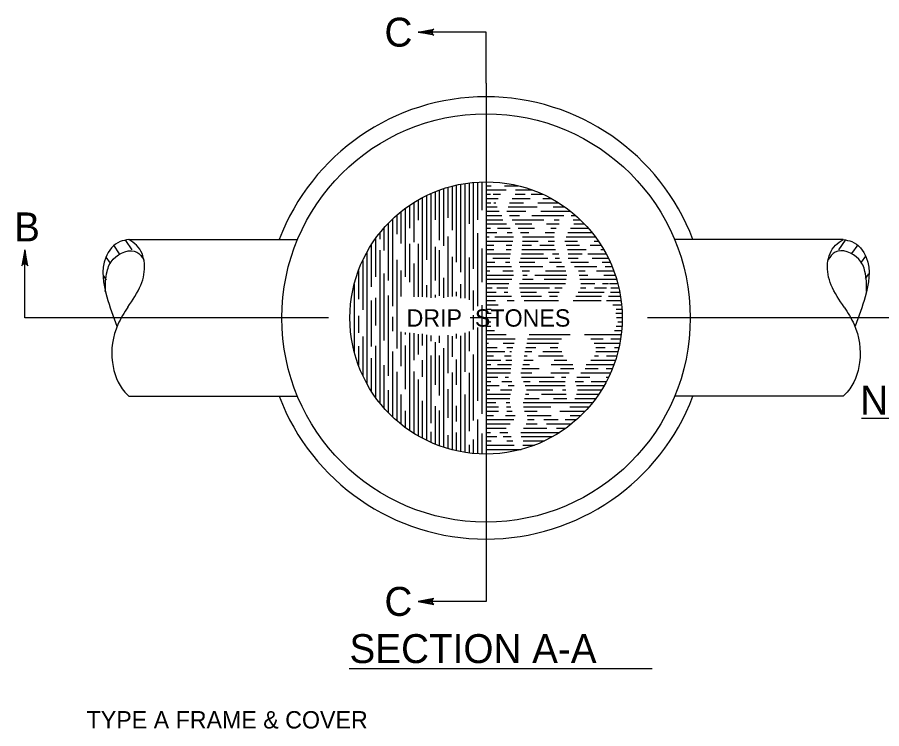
# Model space of a CAD drawing. Extents: x 0.2 to 7.1, y 1.2 to 11.2.
# Drawn here: x 0.3 to 3.289, y 8.396 to 10.856 of the extents above; entities that cross this region are included whole.
import ezdxf

# ---------------------------------------------------------------- set-up
doc = ezdxf.new("R2010")
doc.units = 0
for name, color, linetype in [('DETL-DIMS', 7, 'Continuous'), ('DETL-LINE', 7, 'Continuous'), ('DETL-NOTE', 7, 'Continuous'), ('DETL-PATT', 7, 'Continuous'), ('DETL-TITL', 7, 'Continuous')]:
    doc.layers.add(name, color=color, linetype=linetype)

msp = doc.modelspace()

# ---------------------------------------------------------------- linework, layer by layer
at = {"layer": 'DETL-DIMS'}
for p, q in [((1.9208, 10.8045), (1.6855, 10.8045)), ((1.9208, 10.628), (1.9208, 10.8045)), ((1.9208, 10.628), (1.9208, 9.0129)), ((0.3259, 9.8165), (0.3259, 10.0518)), ((0.5024, 9.8165), (0.3259, 9.8165)), ((1.3755, 9.8165), (0.5024, 9.8165)), ((3.3247, 9.8165), (2.4784, 9.8165)), ((1.9208, 9.0129), (1.9208, 8.8365)), ((1.9208, 8.8365), (1.6855, 8.8365))]:
    msp.add_line(p, q, dxfattribs=at)
for points in [[(1.6855, 10.8045), (1.7403, 10.8148), (1.7361, 10.8119), (1.7339, 10.8082), (1.7333, 10.8045), (1.7339, 10.8008), (1.7361, 10.7972), (1.7403, 10.7942), (1.6855, 10.8045), (1.7361, 10.7972), (1.7339, 10.8008), (1.6855, 10.8045), (1.7333, 10.8045), (1.7339, 10.8082), (1.6855, 10.8045), (1.7361, 10.8119)], [(0.3259, 10.0518), (0.3156, 9.997), (0.3186, 10.0012), (0.3222, 10.0034), (0.3259, 10.004), (0.3296, 10.0034), (0.3333, 10.0012), (0.3362, 9.997), (0.3259, 10.0518), (0.3333, 10.0012), (0.3296, 10.0034), (0.3259, 10.0518), (0.3259, 10.004), (0.3222, 10.0034), (0.3259, 10.0518), (0.3186, 10.0012)], [(1.6855, 8.8365), (1.7403, 8.8262), (1.7361, 8.8291), (1.7339, 8.8328), (1.7333, 8.8365), (1.7339, 8.8401), (1.7361, 8.8438), (1.7403, 8.8467), (1.6855, 8.8365), (1.7361, 8.8438), (1.7339, 8.8401), (1.6855, 8.8365), (1.7333, 8.8365), (1.7339, 8.8328), (1.6855, 8.8365), (1.7361, 8.8291)]]:
    msp.add_lwpolyline(points, dxfattribs=at)
at = {"layer": 'DETL-LINE'}
for p, q in [((0.6855, 10.0874), (1.2689, 10.0874)), ((3.1557, 10.0874), (2.5722, 10.0874)), ((0.6855, 9.5457), (1.2689, 9.5457)), ((3.1557, 9.5457), (2.5722, 9.5457))]:
    msp.add_line(p, q, dxfattribs=at)
for radius in [0.7059, 0.4706]:
    msp.add_circle((1.9208, 9.8165), radius, dxfattribs=at)
for start, end in [(20.7424, 159.2576), (200.7424, 339.2576)]:
    msp.add_arc((1.9208, 9.8165), 0.7647, start, end, dxfattribs=at)
for points in [[(0.6855, 10.0874), (0.6561, 10.0807), (0.606, 10.0252), (0.6096, 9.8901), (0.6447, 9.7881)], [(0.682, 9.8543), (0.7273, 9.9302), (0.7396, 10.0051), (0.7128, 10.0677), (0.6855, 10.0874)], [(3.1592, 9.8543), (3.1139, 9.9302), (3.1016, 10.0051), (3.1284, 10.0677), (3.1557, 10.0874)], [(3.1557, 10.0874), (3.1851, 10.0807), (3.2352, 10.0252), (3.2316, 9.8901), (3.1965, 9.7881)], [(0.6045, 9.9083), (0.6105, 9.9773), (0.6319, 10.0201), (0.7139, 10.0439), (0.7378, 10.0186)], [(3.2366, 9.9083), (3.2307, 9.9773), (3.2093, 10.0201), (3.1272, 10.0439), (3.1034, 10.0186)], [(0.682, 9.8543), (0.6477, 9.7937), (0.6288, 9.6626), (0.6719, 9.56), (0.6855, 9.5457)], [(3.1592, 9.8543), (3.1934, 9.7937), (3.2123, 9.6626), (3.1693, 9.56), (3.1557, 9.5457)]]:
    msp.add_spline(points, degree=3, dxfattribs=at)
at = {"layer": 'DETL-NOTE'}
msp.add_line((3.2189, 9.4698), (3.6066, 9.4698), dxfattribs=at)
at = {"layer": 'DETL-PATT'}
for p, q in [((1.8473, 10.2813), (1.8473, 9.8848)), ((1.862, 10.2834), (1.862, 10.1419)), ((1.8767, 10.285), (1.8767, 9.9859)), ((1.8914, 10.2862), (1.8914, 10.1556)), ((1.9061, 10.2869), (1.9061, 10.1891)), ((1.7443, 10.2528), (1.7443, 10.1563)), ((1.759, 10.2584), (1.759, 10.0855)), ((1.7737, 10.2635), (1.7737, 10.0657)), ((1.7884, 10.2681), (1.7884, 10.1632)), ((1.8031, 10.2722), (1.8031, 10.1205)), ((1.8178, 10.2757), (1.8178, 10.0093)), ((1.8325, 10.2788), (1.8325, 9.975)), ((1.9208, 10.2737), (1.938, 10.2737)), ((1.9208, 10.259), (1.9908, 10.259)), ((1.9846, 10.2737), (2.0323, 10.2737)), ((2.0223, 10.259), (2.081, 10.259)), ((1.6855, 10.2241), (1.6855, 10.1548)), ((1.7002, 10.2322), (1.7002, 9.8892)), ((1.7149, 10.2397), (1.7149, 10.0177)), ((1.7296, 10.2465), (1.7296, 9.8864)), ((1.9208, 10.2443), (1.9356, 10.2443)), ((1.9208, 10.2296), (1.9623, 10.2296)), ((1.9459, 10.2443), (1.9704, 10.2443)), ((2.0115, 10.2296), (2.0738, 10.2296)), ((2.0217, 10.2443), (2.0565, 10.2443)), ((2.0762, 10.2443), (2.1169, 10.2443)), ((2.1165, 10.2296), (2.1462, 10.2296)), ((1.6414, 10.1952), (1.6414, 9.9582)), ((1.6561, 10.2056), (1.6561, 10.1266)), ((1.6708, 10.2152), (1.6708, 10.0786)), ((1.9208, 10.2149), (1.9372, 10.2149)), ((1.9208, 10.2002), (1.9588, 10.2002)), ((1.9482, 10.2149), (1.9549, 10.2149)), ((1.9973, 10.2002), (2.0975, 10.2002)), ((2.0022, 10.2149), (2.0501, 10.2149)), ((2.0999, 10.2149), (2.1713, 10.2149)), ((2.1528, 10.2002), (2.1933, 10.2002)), ((1.612, 10.1716), (1.612, 10.1061)), ((1.6267, 10.1839), (1.6267, 10.0741)), ((1.9208, 10.1855), (1.9662, 10.1855)), ((1.9208, 10.1708), (1.9753, 10.1708)), ((1.9926, 10.1855), (2.0588, 10.1855)), ((2.0016, 10.1708), (2.0367, 10.1708)), ((2.0794, 10.1708), (2.1901, 10.1708)), ((2.1102, 10.1855), (2.2129, 10.1855)), ((2.2154, 10.1708), (2.2306, 10.1708)), ((1.5825, 10.1437), (1.5825, 9.946)), ((1.5973, 10.1583), (1.5973, 9.8575)), ((1.9208, 10.1561), (1.9788, 10.1561)), ((1.9208, 10.1414), (1.9915, 10.1414)), ((2.0114, 10.1561), (2.1204, 10.1561)), ((2.0219, 10.1414), (2.0786, 10.1414)), ((2.1299, 10.1414), (2.1741, 10.1414)), ((2.1568, 10.1561), (2.1735, 10.1561)), ((2.2222, 10.1561), (2.2466, 10.1561)), ((2.2244, 10.1414), (2.2613, 10.1414)), ((1.5531, 10.1103), (1.5531, 10.0893)), ((1.5678, 10.1278), (1.5678, 10.0497)), ((1.8914, 10.1091), (1.8914, 9.8575)), ((1.9208, 10.1267), (1.9364, 10.1267)), ((1.9208, 10.112), (1.9577, 10.112)), ((1.9601, 10.1267), (2.0037, 10.1267)), ((1.9941, 10.112), (2.0112, 10.112)), ((2.0315, 10.1267), (2.0881, 10.1267)), ((2.0403, 10.112), (2.0683, 10.112)), ((2.1252, 10.112), (2.1569, 10.112)), ((2.1449, 10.1267), (2.1636, 10.1267)), ((2.204, 10.112), (2.2871, 10.112)), ((2.2132, 10.1267), (2.2747, 10.1267)), ((0.674, 10.0847), (0.6961, 10.0523)), ((1.5384, 10.0909), (1.5384, 9.959)), ((1.6561, 10.0733), (1.6561, 9.9407)), ((1.6855, 10.0725), (1.6855, 9.89)), ((1.7884, 10.0984), (1.7884, 9.8897)), ((1.9208, 10.0972), (1.9317, 10.0972)), ((1.9208, 10.0825), (2.0128, 10.0825)), ((1.9514, 10.0972), (2.0152, 10.0972)), ((2.0462, 10.0825), (2.1007, 10.0825)), ((2.0468, 10.0972), (2.1562, 10.0972)), ((2.1354, 10.0825), (2.1573, 10.0825)), ((2.1928, 10.0825), (2.2365, 10.0825)), ((2.1972, 10.0972), (2.2985, 10.0972)), ((2.2942, 10.0825), (2.309, 10.0825)), ((3.1404, 10.0515), (3.164, 10.0855)), ((0.6322, 10.0677), (0.6525, 10.038)), ((1.509, 10.0443), (1.509, 9.5887)), ((1.5237, 10.0691), (1.5237, 9.9239)), ((1.5531, 10.0504), (1.5531, 9.5228)), ((1.7443, 10.0626), (1.7443, 9.946)), ((1.759, 10.0512), (1.759, 9.8928)), ((1.9061, 10.0565), (1.9061, 9.9399)), ((1.9208, 10.0678), (1.9475, 10.0678)), ((1.9208, 10.0531), (1.9482, 10.0531)), ((1.9901, 10.0678), (2.0103, 10.0678)), ((1.9901, 10.0531), (2.0078, 10.0531)), ((2.0444, 10.0531), (2.1604, 10.0531)), ((2.0456, 10.0678), (2.0778, 10.0678)), ((2.107, 10.0678), (2.156, 10.0678)), ((2.1973, 10.0678), (2.2444, 10.0678)), ((2.2029, 10.0531), (2.2674, 10.0531)), ((2.2808, 10.0678), (2.3186, 10.0678)), ((2.3171, 10.0531), (2.3276, 10.0531)), ((3.1859, 10.0397), (3.2067, 10.0696)), ((0.6066, 10.027), (0.621, 10.0059)), ((1.4943, 10.0155), (1.4943, 9.8444)), ((1.612, 10.0177), (1.612, 9.7113)), ((1.8031, 10.0276), (1.8031, 9.8906)), ((1.862, 10.0253), (1.862, 9.8793)), ((1.9208, 10.0384), (2.0052, 10.0384)), ((1.9208, 10.0237), (1.923, 10.0237)), ((1.9443, 10.0237), (2.0027, 10.0237)), ((2.0395, 10.0237), (2.1339, 10.0237)), ((2.0429, 10.0384), (2.1189, 10.0384)), ((2.1505, 10.0384), (2.1719, 10.0384)), ((2.1599, 10.0237), (2.1751, 10.0237)), ((2.205, 10.0384), (2.2531, 10.0384)), ((2.205, 10.0237), (2.2389, 10.0237)), ((2.2729, 10.0384), (2.3358, 10.0384)), ((2.2879, 10.0237), (2.3433, 10.0237)), ((3.2182, 10.0089), (3.2333, 10.0306)), ((1.6708, 10.0047), (1.6708, 9.8895)), ((1.9208, 10.009), (1.9514, 10.009)), ((1.9208, 9.9943), (2.0085, 9.9943)), ((1.9877, 10.009), (2.0034, 10.009)), ((2.0353, 10.009), (2.0896, 10.009)), ((2.039, 9.9943), (2.1165, 9.9943)), ((2.1402, 10.009), (2.1819, 10.009)), ((2.1639, 9.9943), (2.192, 9.9943)), ((2.2141, 10.009), (2.2753, 10.009)), ((2.2271, 9.9943), (2.3037, 9.9943)), ((2.3219, 10.009), (2.3502, 10.009)), ((2.3321, 9.9943), (2.3565, 9.9943)), ((0.5967, 9.9631), (0.6079, 9.9468)), ((1.4796, 9.9803), (1.4796, 9.8818)), ((1.5678, 9.9697), (1.5678, 9.7385)), ((1.6267, 9.9803), (1.6267, 9.8903)), ((1.7737, 9.9552), (1.7737, 9.8864)), ((1.9208, 9.9796), (1.934, 9.9796)), ((1.9208, 9.9649), (2.0152, 9.9649)), ((1.9783, 9.9796), (2.0147, 9.9796)), ((2.0452, 9.9796), (2.0707, 9.9796)), ((2.0475, 9.9649), (2.0628, 9.9649)), ((2.0896, 9.9649), (2.1998, 9.9649)), ((2.1268, 9.9796), (2.1966, 9.9796)), ((2.2407, 9.9796), (2.2634, 9.9796)), ((2.2428, 9.9649), (2.2721, 9.9649)), ((2.3021, 9.9796), (2.3622, 9.9796)), ((2.3282, 9.9649), (2.3674, 9.9649)), ((3.2328, 9.9525), (3.2444, 9.9692)), ((1.4649, 9.9332), (1.4649, 9.6998)), ((1.7149, 9.93), (1.7149, 9.8889)), ((1.8325, 9.9331), (1.8325, 9.8845)), ((1.9208, 9.9502), (2.0101, 9.9502)), ((1.9208, 9.9355), (2, 9.9355)), ((2.0367, 9.9355), (2.1949, 9.9355)), ((2.0464, 9.9502), (2.0841, 9.9502)), ((2.1212, 9.9502), (2.1979, 9.9502)), ((2.2451, 9.9502), (2.372, 9.9502)), ((2.2481, 9.9355), (2.2966, 9.9355)), ((2.3234, 9.9355), (2.3444, 9.9355)), ((2.3472, 9.9355), (2.3761, 9.9355)), ((1.5825, 9.8942), (1.5825, 9.6167)), ((1.7443, 9.8965), (1.7443, 9.8872)), ((1.8178, 9.9064), (1.8178, 9.8914)), ((1.8767, 9.9109), (1.8767, 9.8427)), ((1.9208, 9.9208), (1.9419, 9.9208)), ((1.9208, 9.9061), (1.9554, 9.9061)), ((1.9585, 9.9208), (1.9966, 9.9208)), ((1.9838, 9.9061), (1.9961, 9.9061)), ((2.0364, 9.9208), (2.1402, 9.9208)), ((2.0396, 9.9061), (2.0952, 9.9061)), ((2.137, 9.9061), (2.1739, 9.9061)), ((2.1591, 9.9208), (2.1837, 9.9208)), ((2.2393, 9.9061), (2.3286, 9.9061)), ((2.2472, 9.9208), (2.2658, 9.9208)), ((2.2958, 9.9208), (2.337, 9.9208)), ((2.3509, 9.9061), (2.3828, 9.9061)), ((2.3517, 9.9208), (2.3797, 9.9208)), ((1.5237, 9.8767), (1.5237, 9.7179)), ((1.5384, 9.8866), (1.5384, 9.79)), ((1.9208, 9.8914), (2.0091, 9.8914)), ((1.9208, 9.8767), (1.953, 9.8767)), ((1.9933, 9.8767), (2.0182, 9.8767)), ((2.0424, 9.8914), (2.1125, 9.8914)), ((2.0529, 9.8767), (2.171, 9.8767)), ((2.1402, 9.8914), (2.1682, 9.8914)), ((2.2224, 9.8767), (2.3183, 9.8767)), ((2.231, 9.8914), (2.3203, 9.8914)), ((2.3376, 9.8767), (2.3875, 9.8767)), ((2.3441, 9.8914), (2.3854, 9.8914)), ((1.9061, 9.8603), (1.9061, 9.4845)), ((1.9208, 9.862), (1.9622, 9.862)), ((1.9208, 9.8472), (1.939, 9.8472)), ((1.9208, 9.8325), (1.939, 9.8325)), ((2.3593, 9.862), (2.3892, 9.862)), ((2.3693, 9.8325), (2.3911, 9.8325)), ((2.3711, 9.8472), (2.3904, 9.8472)), ((1.4796, 9.8237), (1.4796, 9.7656)), ((1.5973, 9.8209), (1.5973, 9.7713)), ((1.9626, 9.8165), (1.8658, 9.8165)), ((1.8767, 9.8261), (1.8767, 9.7769)), ((1.9208, 9.8178), (1.9372, 9.8178)), ((1.9208, 9.8031), (1.9372, 9.8031)), ((2.3715, 9.8178), (2.3914, 9.8178)), ((2.3765, 9.8031), (2.3912, 9.8031)), ((1.8914, 9.7835), (1.8914, 9.5295)), ((1.9208, 9.7884), (1.9376, 9.7884)), ((1.9208, 9.7737), (1.9504, 9.7737)), ((2.3647, 9.7737), (2.3894, 9.7737)), ((2.3706, 9.7884), (2.3905, 9.7884)), ((1.4943, 9.7525), (1.4943, 9.6176)), ((1.6267, 9.7688), (1.6267, 9.6504)), ((1.6414, 9.7667), (1.6414, 9.7591)), ((1.6561, 9.7645), (1.6561, 9.4274)), ((1.6708, 9.7634), (1.6708, 9.671)), ((1.6855, 9.7609), (1.6855, 9.6897)), ((1.7002, 9.7615), (1.7002, 9.7207)), ((1.7149, 9.7585), (1.7149, 9.3934)), ((1.7296, 9.7557), (1.7296, 9.7357)), ((1.759, 9.7543), (1.759, 9.731)), ((1.7884, 9.7565), (1.7884, 9.6251)), ((1.8031, 9.7541), (1.8031, 9.6822)), ((1.8178, 9.7615), (1.8178, 9.746)), ((1.8325, 9.7549), (1.8325, 9.3543)), ((1.8473, 9.7651), (1.8473, 9.6307)), ((1.862, 9.7695), (1.862, 9.7019)), ((1.9208, 9.759), (1.9904, 9.759)), ((1.9208, 9.7443), (2.0217, 9.7443)), ((2.0646, 9.7443), (2.1816, 9.7443)), ((2.0699, 9.759), (2.2113, 9.759)), ((2.2607, 9.759), (2.3878, 9.759)), ((2.2825, 9.7443), (2.3254, 9.7443)), ((2.3527, 9.7443), (2.3858, 9.7443)), ((1.4796, 9.7188), (1.4796, 9.6528)), ((1.5384, 9.7197), (1.5384, 9.5422)), ((1.6414, 9.7207), (1.6414, 9.5698)), ((1.7443, 9.7328), (1.7443, 9.5857)), ((1.9208, 9.7296), (1.9289, 9.7296)), ((1.9208, 9.7149), (1.9593, 9.7149)), ((1.9805, 9.7296), (2.0175, 9.7296)), ((1.9926, 9.7149), (2.0134, 9.7149)), ((2.058, 9.7149), (2.0928, 9.7149)), ((2.0613, 9.7296), (2.171, 9.7296)), ((2.1423, 9.7149), (2.1684, 9.7149)), ((2.2946, 9.7296), (2.3833, 9.7296)), ((2.3001, 9.7149), (2.3325, 9.7149)), ((2.3648, 9.7149), (2.3803, 9.7149)), ((1.5973, 9.701), (1.5973, 9.4748)), ((1.7296, 9.6869), (1.7296, 9.4527)), ((1.759, 9.6869), (1.759, 9.5482)), ((1.7737, 9.7122), (1.7737, 9.3695)), ((1.8767, 9.6907), (1.8767, 9.462)), ((1.9208, 9.7002), (1.9856, 9.7002)), ((1.9208, 9.6855), (1.9461, 9.6855)), ((1.9845, 9.6855), (2.0079, 9.6855)), ((2.0028, 9.7002), (2.0092, 9.7002)), ((2.0527, 9.6855), (2.0634, 9.6855)), ((2.0547, 9.7002), (2.0796, 9.7002)), ((2.1019, 9.6855), (2.1875, 9.6855)), ((2.117, 9.7002), (2.1822, 9.7002)), ((2.2955, 9.6855), (2.3092, 9.6855)), ((2.3001, 9.7002), (2.3768, 9.7002)), ((2.3375, 9.6855), (2.3728, 9.6855)), ((1.5237, 9.6776), (1.5237, 9.5639)), ((1.5678, 9.6532), (1.5678, 9.5053)), ((1.7002, 9.6701), (1.7002, 9.6129)), ((1.8178, 9.6729), (1.8178, 9.5857)), ((1.9208, 9.6708), (1.9714, 9.6708)), ((1.9208, 9.6561), (1.937, 9.6561)), ((1.9603, 9.6561), (2.0082, 9.6561)), ((1.9896, 9.6708), (2.0094, 9.6708)), ((2.0479, 9.6561), (2.0715, 9.6561)), ((2.0509, 9.6708), (2.0837, 9.6708)), ((2.1454, 9.6561), (2.2212, 9.6561)), ((2.1565, 9.6708), (2.2006, 9.6708)), ((2.2669, 9.6561), (2.3632, 9.6561)), ((2.2826, 9.6708), (2.3682, 9.6708)), ((1.612, 9.6307), (1.612, 9.4614)), ((1.6708, 9.6316), (1.6708, 9.4178)), ((1.8031, 9.6279), (1.8031, 9.3609)), ((1.862, 9.627), (1.862, 9.4246)), ((1.9208, 9.6414), (2.0069, 9.6414)), ((1.9208, 9.6267), (2.0052, 9.6267)), ((2.0414, 9.6267), (2.0796, 9.6267)), ((2.0444, 9.6414), (2.1039, 9.6414)), ((2.1444, 9.6267), (2.2083, 9.6267)), ((2.1787, 9.6414), (2.2237, 9.6414)), ((2.2485, 9.6267), (2.3514, 9.6267)), ((2.2637, 9.6414), (2.3082, 9.6414)), ((2.3365, 9.6414), (2.3576, 9.6414)), ((1.6855, 9.6035), (1.6855, 9.409)), ((1.9208, 9.612), (1.9613, 9.612)), ((1.9208, 9.5972), (1.937, 9.5972)), ((1.9754, 9.5972), (2.0097, 9.5972)), ((1.9866, 9.612), (1.9982, 9.612)), ((2.0438, 9.612), (2.1565, 9.612)), ((2.0504, 9.5972), (2.0736, 9.5972)), ((2.1039, 9.5972), (2.1939, 9.5972)), ((2.1818, 9.612), (2.1971, 9.612)), ((2.2293, 9.5972), (2.2576, 9.5972)), ((2.235, 9.612), (2.2799, 9.612)), ((2.2839, 9.5972), (2.3372, 9.5972)), ((2.3355, 9.612), (2.3446, 9.612)), ((1.5825, 9.567), (1.5825, 9.4893)), ((1.7884, 9.5707), (1.7884, 9.4714)), ((1.9208, 9.5825), (1.9663, 9.5825)), ((1.9208, 9.5678), (1.934, 9.5678)), ((1.9704, 9.5678), (2.0094, 9.5678)), ((1.9967, 9.5825), (2.0179, 9.5825)), ((2.0564, 9.5825), (2.194, 9.5825)), ((2.0611, 9.5678), (2.1514, 9.5678)), ((2.1848, 9.5678), (2.1969, 9.5678)), ((2.2338, 9.5825), (2.3291, 9.5825)), ((2.2368, 9.5678), (2.3203, 9.5678)), ((1.6267, 9.552), (1.6267, 9.4492)), ((1.8473, 9.552), (1.8473, 9.3517)), ((1.9208, 9.5531), (2.0048, 9.5531)), ((1.9208, 9.5384), (2.0028, 9.5384)), ((2.0532, 9.5384), (2.1049, 9.5384)), ((2.0574, 9.5531), (2.0685, 9.5531)), ((2.112, 9.5531), (2.1974, 9.5531)), ((2.1535, 9.5384), (2.1997, 9.5384)), ((2.2282, 9.5384), (2.3004, 9.5384)), ((2.2333, 9.5531), (2.3108, 9.5531)), ((1.7002, 9.5295), (1.7002, 9.4008)), ((1.7443, 9.5117), (1.7443, 9.3803)), ((1.8178, 9.5126), (1.8178, 9.4583)), ((1.9208, 9.5237), (1.9542, 9.5237)), ((1.9208, 9.509), (1.9643, 9.509)), ((1.9906, 9.5237), (2.0028, 9.5237)), ((1.9916, 9.509), (2.0061, 9.509)), ((2.0486, 9.5237), (2.2892, 9.5237)), ((2.05, 9.509), (2.1444, 9.509)), ((2.2101, 9.509), (2.277, 9.509)), ((1.6414, 9.4958), (1.6414, 9.4379)), ((1.759, 9.4967), (1.759, 9.3746)), ((1.9208, 9.4943), (1.9643, 9.4943)), ((1.9208, 9.4796), (1.9461, 9.4796)), ((1.9876, 9.4796), (2.0211, 9.4796)), ((1.9926, 9.4943), (2.0108, 9.4943)), ((2.0542, 9.4943), (2.0978, 9.4943)), ((2.0628, 9.4796), (2.1464, 9.4796)), ((2.1757, 9.4943), (2.2638, 9.4943)), ((2.2121, 9.4796), (2.2493, 9.4796)), ((1.8914, 9.4658), (1.8914, 9.3469)), ((1.9208, 9.4649), (2.0169, 9.4649)), ((1.9208, 9.4502), (2.0047, 9.4502)), ((2.0597, 9.4502), (2.0978, 9.4502)), ((2.0636, 9.4649), (2.0867, 9.4649)), ((2.1201, 9.4649), (2.1706, 9.4649)), ((2.1292, 9.4502), (2.2162, 9.4502)), ((2.1939, 9.4649), (2.2335, 9.4649)), ((1.7296, 9.4227), (1.7296, 9.3865)), ((1.8178, 9.4208), (1.8178, 9.3573)), ((1.9061, 9.4171), (1.9061, 9.3462)), ((1.9208, 9.4355), (1.9906, 9.4355)), ((1.9208, 9.4208), (1.936, 9.4208)), ((1.9684, 9.4208), (1.9961, 9.4208)), ((2.0414, 9.4208), (2.1754, 9.4208)), ((2.0499, 9.4355), (2.1312, 9.4355)), ((2.1646, 9.4355), (2.1969, 9.4355)), ((1.7884, 9.4114), (1.7884, 9.3649)), ((1.8767, 9.3964), (1.8767, 9.348)), ((1.9208, 9.4061), (1.9582, 9.4061)), ((1.9208, 9.3914), (1.938, 9.3914)), ((1.9795, 9.4061), (2.0071, 9.4061)), ((1.9926, 9.3914), (2.0133, 9.3914)), ((2.0422, 9.4061), (2.151, 9.4061)), ((2.0487, 9.3914), (2.1225, 9.3914)), ((1.862, 9.3777), (1.862, 9.3496)), ((1.9208, 9.3767), (2.0176, 9.3767)), ((1.9208, 9.362), (2.0425, 9.362)), ((2.0474, 9.3767), (2.088, 9.3767))]:
    msp.add_line(p, q, dxfattribs=at)
at = {"layer": 'DETL-TITL'}
msp.add_line((1.448, 8.6047), (2.4954, 8.6047), dxfattribs=at)

# ---------------------------------------------------------------- texts
at = {"layer": 'DETL-NOTE'}
for s, height, p in [('C', 0.1, (1.5695, 10.7545)), ('B', 0.1, (0.2892, 10.0812)), ('DRIP  STONES', 0.06, (1.646, 9.7865)), ('NOTE', 0.1, (3.2143, 9.4823)), ('C', 0.1, (1.5695, 8.7865)), ('TYPE A FRAME & COVER', 0.06, (0.5398, 8.3972))]:
    msp.add_text(s, height=height, dxfattribs=at).set_placement(p)
at = {"layer": 'DETL-TITL'}
msp.add_text('SECTION A-A', height=0.1, dxfattribs=at).set_placement((1.4486, 8.6233))

doc.saveas('drawing.dxf')
